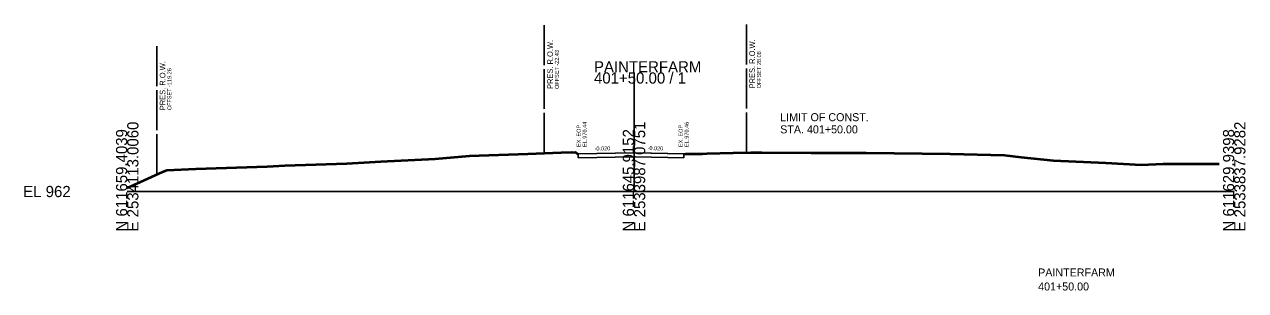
# Model space of a CAD drawing. Extents: x -26 to 453, y 80 to 2034.
# Drawn here: x -25.7 to 279.5, y 1475.2 to 1541.8 of the extents above; entities that cross this region are included whole.
import ezdxf

# ---------------------------------------------------------------- set-up
doc = ezdxf.new("R2010")
doc.units = 0
for name, color, linetype in [('DESIGN - SHEET - Light Grid', 7, 'Continuous'), ('DESIGN - TRANSPORTATION - Proposed Layout Patterning', 7, 'Continuous'), ('DESIGN - TRANSPORTATION - Text', 7, 'Continuous'), ('DESIGN - TYPICAL - Finished Grade and Subgrade', 7, 'Continuous'), ('DESIGN - TYPICAL - Finished Grade Slopes Text', 7, 'Continuous'), ('DESIGN - TYPICAL - Warning Text', 7, 'Continuous'), ('SURVEY - GROUND - Bottom of Topsoil Layer', 7, 'Continuous'), ('SURVEY - GROUND - Existing Pavement Layer', 7, 'Continuous'), ('SURVEY - GROUND - Existing Pavement Text', 7, 'Continuous'), ('SURVEY - GROUND - Top of Ground', 7, 'Continuous'), ('SURVEY - PROPERTY - ROW Lines', 7, 'Continuous'), ('SURVEY - PROPERTY - ROW Lines Text', 7, 'Continuous')]:
    doc.layers.add(name, color=color, linetype=linetype)

msp = doc.modelspace()

# ---------------------------------------------------------------- linework, layer by layer
at = {"layer": 'DESIGN - SHEET - Light Grid'}
for p, q in [((126.65, 1500), (126.65, 1529.79)), ((0, 1500), (126.65, 1500)), ((126.65, 1500), (276.65, 1500))]:
    msp.add_line(p, q, dxfattribs=at)
at = {"layer": 'DESIGN - TRANSPORTATION - Proposed Layout Patterning'}
for q in [(112.67, 1509.41), (139.13, 1509.44)]:
    msp.add_line((126.65, 1509.68), q, dxfattribs=at)
at = {"layer": 'DESIGN - TYPICAL - Finished Grade and Subgrade'}
for p, q in [((111.17, 1509.92), (111.11, 1509.91)), ((139.13, 1509.44), (139.13, 1508.81))]:
    msp.add_line(p, q, dxfattribs=at)
at = {"layer": 'SURVEY - GROUND - Bottom of Topsoil Layer'}
for p, q in [((63.42, 1507.31), (76.94, 1508.04)), ((76.94, 1508.04), (85.52, 1508.78)), ((85.52, 1508.78), (100.1, 1509.23)), ((100.1, 1509.23), (108.47, 1509.58)), ((108.47, 1509.58), (112.02, 1509.68)), ((112.02, 1509.68), (112.67, 1509.19)), ((112.67, 1509.19), (112.67, 1509.44)), ((139.13, 1509.21), (139.13, 1509.46)), ((139.13, 1509.21), (139.53, 1509.23)), ((139.53, 1509.23), (143.8, 1509.29)), ((143.8, 1509.29), (144.85, 1509.32)), ((144.85, 1509.32), (151.4, 1509.51)), ((151.4, 1509.51), (155.81, 1509.55)), ((155.81, 1509.55), (158.57, 1509.56)), ((158.57, 1509.56), (170.96, 1509.51)), ((170.96, 1509.51), (184.63, 1509.47)), ((184.63, 1509.47), (205.64, 1509.24)), ((205.64, 1509.24), (219.28, 1508.94)), ((219.28, 1508.94), (223.4, 1508.45)), ((223.4, 1508.45), (231.46, 1507.6)), ((3.34, 1502.27), (8.8, 1504.72)), ((8.8, 1504.72), (9.89, 1505.2)), ((9.89, 1505.2), (17.12, 1505.5)), ((17.12, 1505.5), (34.97, 1506.11)), ((34.97, 1506.11), (39.42, 1506.36)), ((39.42, 1506.36), (54.87, 1506.85)), ((54.87, 1506.85), (63.42, 1507.31)), ((231.46, 1507.6), (244.58, 1506.97)), ((244.58, 1506.97), (253.38, 1506.49)), ((253.38, 1506.49), (258.88, 1506.72)), ((258.88, 1506.72), (272.91, 1506.78)), ((0, 1500.77), (3.34, 1502.27))]:
    msp.add_line(p, q, dxfattribs=at)
at = {"layer": 'SURVEY - GROUND - Existing Pavement Layer'}
for p, q in [((112.67, 1509.44), (112.67, 1508.44)), ((139.13, 1508.46), (139.13, 1509.46))]:
    msp.add_line(p, q, dxfattribs=at)
msp.add_lwpolyline([(112.67, 1508.44), (126.63, 1508.68), (127.05, 1508.68), (139.13, 1508.46)], dxfattribs=at)
at = {"layer": 'SURVEY - GROUND - Top of Ground'}
msp.add_lwpolyline([(0, 1501.02), (3.34, 1502.52), (8.8, 1504.97), (9.89, 1505.45), (17.12, 1505.75), (34.97, 1506.36), (39.42, 1506.61), (54.87, 1507.1), (63.42, 1507.56), (76.94, 1508.29), (85.52, 1509.03), (100.1, 1509.48), (108.47, 1509.83), (112.02, 1509.93), (112.67, 1509.44), (126.63, 1509.68), (127.06, 1509.68), (139.13, 1509.46), (139.53, 1509.48), (143.8, 1509.54), (144.85, 1509.57), (151.4, 1509.76), (155.81, 1509.8), (158.57, 1509.81), (170.96, 1509.76), (184.63, 1509.72), (205.64, 1509.49), (219.28, 1509.19), (223.4, 1508.7), (231.46, 1507.85), (244.58, 1507.22), (253.38, 1506.74), (258.88, 1506.97), (272.91, 1507.03)], dxfattribs=at)
at = {"layer": 'SURVEY - PROPERTY - ROW Lines'}
for p, q in [((104.22, 1531.64), (104.22, 1541.64)), ((154.73, 1531.79), (154.73, 1541.79)), ((7.39, 1526.33), (7.39, 1536.33)), ((104.22, 1520.64), (104.22, 1530.64)), ((154.73, 1520.79), (154.73, 1530.79)), ((7.39, 1515.33), (7.39, 1525.33)), ((104.22, 1509.64), (104.22, 1519.64)), ((154.73, 1509.79), (154.73, 1519.79)), ((7.39, 1504.33), (7.39, 1514.33))]:
    msp.add_line(p, q, dxfattribs=at)

# ---------------------------------------------------------------- texts
at = {"layer": 'DESIGN - SHEET - Light Grid'}
for s, p in [('PAINTERFARM', (116.65, 1529.79)), ('401+50.00 / 1', (116.65, 1526.99)), ('EL 962', (-26, 1498.6))]:
    msp.add_text(s, height=2.8, dxfattribs=at).set_placement(p)
for s, p in [('E 2534113.0060', (2.8, 1490)), ('E 2533987.0751', (129.45, 1490)), ('E 2533837.9282', (279.45, 1490)), ('N 611659.4039', (0, 1490)), ('N 611645.9152', (126.65, 1490)), ('N 611629.9398', (276.65, 1490))]:
    msp.add_text(s, height=2.8, rotation=90, dxfattribs=at).set_placement(p)
at = {"layer": 'DESIGN - TRANSPORTATION - Text'}
for s, p in [('LIMIT OF CONST.', (163.19, 1517.59)), ('STA. 401+50.00', (163.19, 1514.54))]:
    msp.add_text(s, height=2, dxfattribs=at).set_placement(p)
at = {"layer": 'DESIGN - TYPICAL - Finished Grade Slopes Text'}
for rotation, p in [(1.1458, (116.81, 1510.24)), (358.8542, (130.04, 1510.37))]:
    msp.add_text('-0.020', height=1, rotation=rotation, dxfattribs=at).set_placement(p)
at = {"layer": 'DESIGN - TYPICAL - Warning Text'}
for s, p in [('PAINTERFARM', (227.65, 1478.75)), ('401+50.00', (227.65, 1475.25))]:
    msp.add_text(s, height=2, dxfattribs=at).set_placement(p)
at = {"layer": 'SURVEY - GROUND - Existing Pavement Text'}
for s, p in [('EL.970.44', (114.83, 1511.14)), ('EL.970.46', (140.31, 1511.14)), ('EX. EOP', (113.33, 1511.14)), ('EX. EOP', (138.81, 1511.14))]:
    msp.add_text(s, height=1, rotation=90, dxfattribs=at).set_placement(p)
at = {"layer": 'SURVEY - PROPERTY - ROW Lines Text'}
for s, height, p in [('PRES. R.O.W.', 1.4, (106.37, 1525.64)), ('PRES. R.O.W.', 1.4, (156.88, 1525.79)), ('PRES. R.O.W.', 1.4, (9.54, 1520.33)), ('OFFSET -22.43', 1, (107.87, 1525.64)), ('OFFSET 28.08', 1, (158.38, 1525.79)), ('OFFSET -119.26', 1, (11.04, 1520.33))]:
    msp.add_text(s, height=height, rotation=90, dxfattribs=at).set_placement(p)

doc.saveas('drawing.dxf')
